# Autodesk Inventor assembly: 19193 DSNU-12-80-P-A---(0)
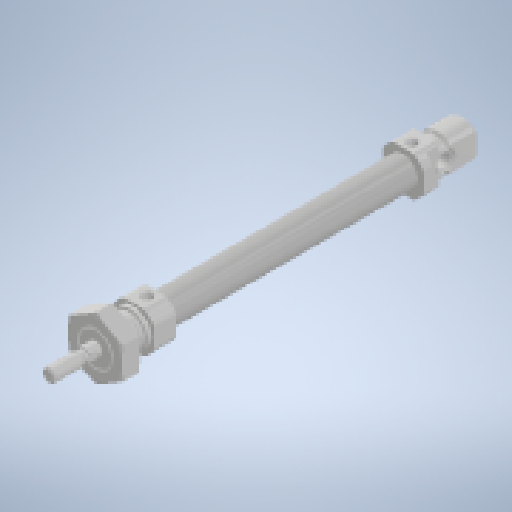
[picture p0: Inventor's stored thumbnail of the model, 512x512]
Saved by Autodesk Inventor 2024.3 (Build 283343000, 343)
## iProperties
Company: CADENAS
Created: 2024-11
Part Number: 19193 DSNU-12-80-P-A---(0)
Description: STEP AP214
Document SubType Name: Assembly
Designer: ruhr
Title: 19193_DSNU-12-80-P-A
Author: License CC BY-ND 4.0
Sending System: PARTsolutions
Preprocessor: ST-DEVELOPER v19.3
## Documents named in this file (5)
- C:\Users\ruhr\Downloads\PARTserver0202411291136211484952210e898ce\19193_DSNU-12-80-P-A\19193_DSNU-12-80-P-A\19193_DSNU-12-80-P-A.iam
- C:\Users\ruhr\Downloads\PARTserver0202411291136211484952210e898ce\19193_DSNU-12-80-P-A\19193_DSNU-12-80-P-A\19193 DSNU-12-80-P---(A----0-ZR).ipt
- C:\Users\ruhr\Downloads\PARTserver0202411291136211484952210e898ce\19193_DSNU-12-80-P-A\19193_DSNU-12-80-P-A\DIN-439-B - M16x1.5(F).ipt
- C:\Users\ruhr\Downloads\PARTserver0202411291136211484952210e898ce\19193_DSNU-12-80-P-A\19193_DSNU-12-80-P-A\19193 DSNU-12-80-P---(A---00--0-KS).ipt
- C:\Users\ruhr\OneDrive - Mercantec\Dokumenter\DigiTwinVideo\Pusher plate 2.ipt
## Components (4 placed, 4 different names)
1. NAUO1
2. NAUO2
3. NAUO3 — Flush:1
4. Pusher plate 2:1 — Flush:1
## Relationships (1: Flush 1)
- Flush:1: NAUO3 ↔ Pusher plate 2:1
